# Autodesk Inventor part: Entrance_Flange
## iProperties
Shininess: 64.0
Length Units: 11269
Angle Units: 11279
Time Units: 11290
Mass Units: 11283
Length Display Precision: 3
Angle Display Precision: 2
Compacted: True
Part Number: Entrance_Flange
Document SubType Name: Modeling
Created: 2004-07
Designer: John Blackburn
Manufacturer: Standard
Standards Organization: Custom
Material: Stainless Steel, Austenitic
Description: Mucap, Entrance Flange
Density: 0.0
Volumn: 0.0
Area: 0.0
PropertySet Name: Model Information
Control State: 0
Master: False
Checked Out: False
Author: John Blackburn
Title: TPC Entrance Flange
Subject: MuCap
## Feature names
1. Extrusion1
2. Hole1
3. Circular Pattern1
4. Extrusion2
5. Chamfer1
6. Hole2
7. Circular Pattern2
8. Hole3
9. Circular Pattern3
10. Hole4
11. Hole5
12. Extrusion3
13. Extrusion4
14. Extrusion5
15. Hole6
